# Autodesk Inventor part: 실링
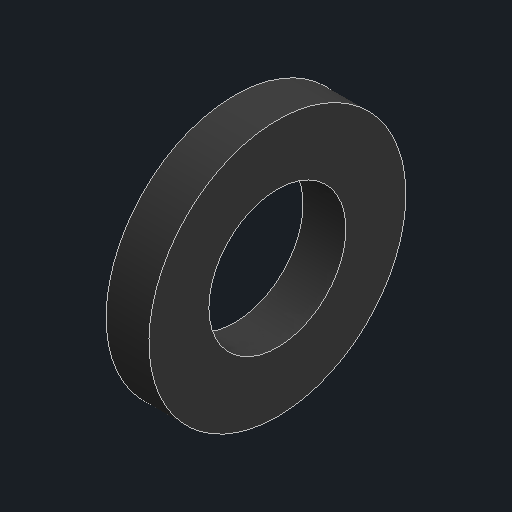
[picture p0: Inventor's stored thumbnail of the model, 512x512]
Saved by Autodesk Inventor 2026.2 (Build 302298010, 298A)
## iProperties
Created: 2026-03
Part Number: 실링
Material: 고무, 실리콘
Document SubType Name: Modeling
Designer: PC2-02
Density: 1.25 g/cm^3
Appearance: 기본값
Author: jhkim
Sending System: Autodesk Inventor 2026
Preprocessor: ST-DEVELOPER v20.1
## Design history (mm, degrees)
feature "솔리드1"
node "솔리드2"
